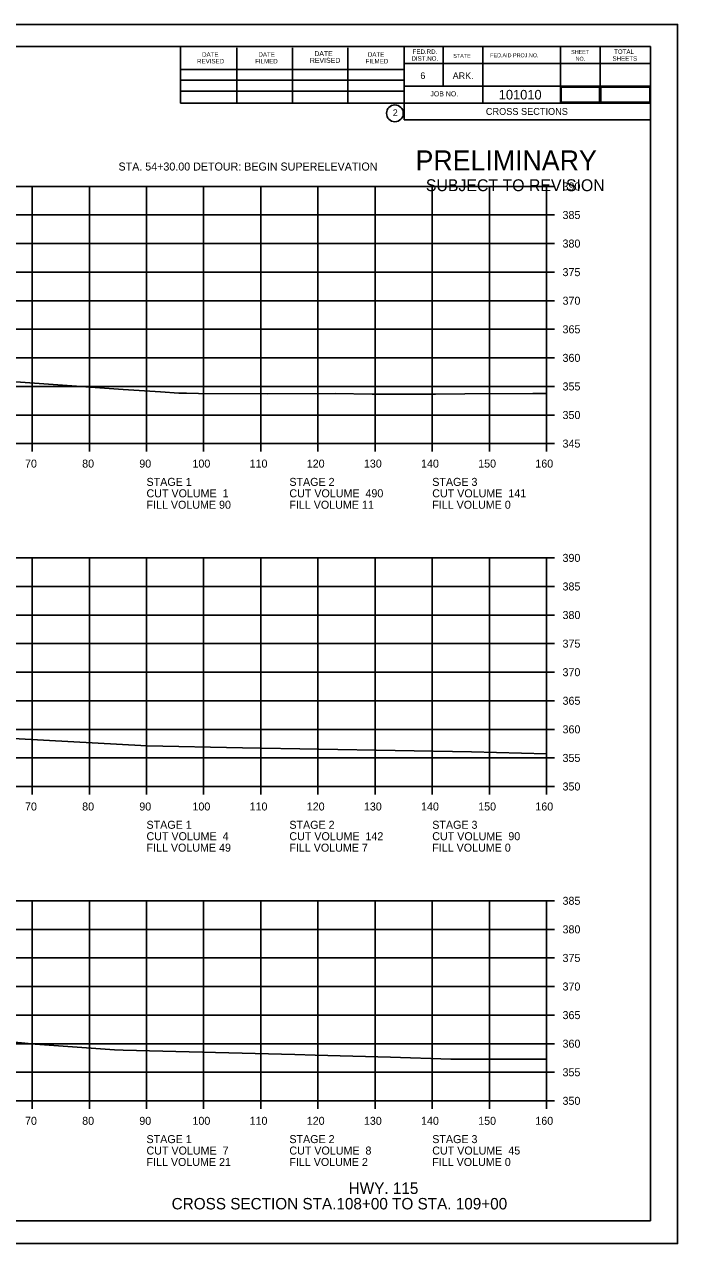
# Model space of a CAD drawing. Extents: x 1630712 to 1632516, y 782146 to 785403.
# Drawn here: x 1632401.6 to 1632515.9, y 783696.6 to 783910 of the extents above; entities that cross this region are included whole.
import ezdxf

# ---------------------------------------------------------------- set-up
doc = ezdxf.new("R2010")
doc.units = 0
for name, color, linetype in [('Page Number', 7, 'Continuous'), ('R_Annot', 7, 'Continuous'), ('R_Axis', 7, 'Continuous'), ('R_Axis Annot', 7, 'Continuous'), ('R_Border', 7, 'Continuous'), ('R_Border Notes', 7, 'Continuous'), ('R_Border Prem', 7, 'Continuous'), ('R_Draft', 7, 'Continuous'), ('R_Exist Surface', 7, 'Continuous'), ('R_Grid', 7, 'Continuous'), ('R_No Plot', 7, 'Continuous'), ('Total_Pages', 7, 'Continuous')]:
    doc.layers.add(name, color=color, linetype=linetype)

msp = doc.modelspace()

# ---------------------------------------------------------------- linework, layer by layer
at = {"layer": 'Page Number'}
msp.add_lwpolyline([(1632495.54, 783896.35), (1632502.21, 783896.35), (1632502.21, 783898.99), (1632495.54, 783898.99)], close=True, dxfattribs=at)
at = {"layer": 'R_Axis'}
for p, q in [((1632492.96, 783836.62), (1632492.96, 783881.62)), ((1632494.36, 783881.62), (1632492.96, 783881.62)), ((1632494.36, 783876.62), (1632492.96, 783876.62)), ((1632494.36, 783871.62), (1632492.96, 783871.62)), ((1632494.36, 783866.62), (1632492.96, 783866.62)), ((1632494.36, 783861.62), (1632492.96, 783861.62)), ((1632494.36, 783856.62), (1632492.96, 783856.62)), ((1632494.36, 783851.62), (1632492.96, 783851.62)), ((1632494.36, 783846.62), (1632492.96, 783846.62)), ((1632494.36, 783841.62), (1632492.96, 783841.62)), ((1632212.96, 783836.62), (1632492.96, 783836.62)), ((1632402.96, 783835.22), (1632402.96, 783836.62)), ((1632412.96, 783835.22), (1632412.96, 783836.62)), ((1632422.96, 783835.22), (1632422.96, 783836.62)), ((1632432.96, 783835.22), (1632432.96, 783836.62)), ((1632442.96, 783835.22), (1632442.96, 783836.62)), ((1632452.96, 783835.22), (1632452.96, 783836.62)), ((1632462.96, 783835.22), (1632462.96, 783836.62)), ((1632472.96, 783835.22), (1632472.96, 783836.62)), ((1632482.96, 783835.22), (1632482.96, 783836.62)), ((1632492.96, 783835.22), (1632492.96, 783836.62)), ((1632494.36, 783836.62), (1632492.96, 783836.62)), ((1632492.96, 783776.62), (1632492.96, 783816.62)), ((1632494.36, 783816.62), (1632492.96, 783816.62)), ((1632494.36, 783811.62), (1632492.96, 783811.62)), ((1632494.36, 783806.62), (1632492.96, 783806.62)), ((1632494.36, 783801.62), (1632492.96, 783801.62)), ((1632494.36, 783796.62), (1632492.96, 783796.62)), ((1632494.36, 783791.62), (1632492.96, 783791.62)), ((1632494.36, 783786.62), (1632492.96, 783786.62)), ((1632494.36, 783781.62), (1632492.96, 783781.62)), ((1632212.96, 783776.62), (1632492.96, 783776.62)), ((1632402.96, 783775.22), (1632402.96, 783776.62)), ((1632412.96, 783775.22), (1632412.96, 783776.62)), ((1632422.96, 783775.22), (1632422.96, 783776.62)), ((1632432.96, 783775.22), (1632432.96, 783776.62)), ((1632442.96, 783775.22), (1632442.96, 783776.62)), ((1632452.96, 783775.22), (1632452.96, 783776.62)), ((1632462.96, 783775.22), (1632462.96, 783776.62)), ((1632472.96, 783775.22), (1632472.96, 783776.62)), ((1632482.96, 783775.22), (1632482.96, 783776.62)), ((1632492.96, 783775.22), (1632492.96, 783776.62)), ((1632494.36, 783776.62), (1632492.96, 783776.62)), ((1632492.96, 783721.62), (1632492.96, 783756.62)), ((1632494.36, 783756.62), (1632492.96, 783756.62)), ((1632494.36, 783751.62), (1632492.96, 783751.62)), ((1632494.36, 783746.62), (1632492.96, 783746.62)), ((1632494.36, 783741.62), (1632492.96, 783741.62)), ((1632494.36, 783736.62), (1632492.96, 783736.62)), ((1632494.36, 783731.62), (1632492.96, 783731.62)), ((1632494.36, 783726.62), (1632492.96, 783726.62)), ((1632212.96, 783721.62), (1632492.96, 783721.62)), ((1632402.96, 783720.22), (1632402.96, 783721.62)), ((1632412.96, 783720.22), (1632412.96, 783721.62)), ((1632422.96, 783720.22), (1632422.96, 783721.62)), ((1632432.96, 783720.22), (1632432.96, 783721.62)), ((1632442.96, 783720.22), (1632442.96, 783721.62)), ((1632452.96, 783720.22), (1632452.96, 783721.62)), ((1632462.96, 783720.22), (1632462.96, 783721.62)), ((1632472.96, 783720.22), (1632472.96, 783721.62)), ((1632482.96, 783720.22), (1632482.96, 783721.62)), ((1632492.96, 783720.22), (1632492.96, 783721.62)), ((1632494.36, 783721.62), (1632492.96, 783721.62))]:
    msp.add_line(p, q, dxfattribs=at)
at = {"layer": 'R_Border'}
for p, q in [((1632194.96, 783906.08), (1632511.14, 783906.08)), ((1632428.88, 783896.2), (1632428.88, 783906.08)), ((1632438.74, 783896.2), (1632438.74, 783905.88)), ((1632448.5, 783896.2), (1632448.5, 783905.88)), ((1632458.18, 783896.2), (1632458.18, 783905.88)), ((1632468.04, 783906.08), (1632468.04, 783893.28)), ((1632474.88, 783906.08), (1632474.88, 783899.14)), ((1632481.82, 783906.08), (1632481.82, 783896.2)), ((1632495.4, 783906.08), (1632495.4, 783896.2)), ((1632502.34, 783906.08), (1632502.34, 783896.2)), ((1632511.14, 783700.62), (1632511.14, 783906.08)), ((1632511.14, 783903.14), (1632468.04, 783903.14)), ((1632511.14, 783903.16), (1632511.14, 783903.16)), ((1632428.88, 783902.06), (1632468.04, 783902.06)), ((1632428.88, 783900.2), (1632468.04, 783900.2)), ((1632511.14, 783899.14), (1632468.04, 783899.14)), ((1632471, 783899.14), (1632511.14, 783899.14)), ((1632428.88, 783896.2), (1632428.88, 783898.26)), ((1632428.88, 783898.26), (1632468.04, 783898.26)), ((1632511.14, 783896.2), (1632428.88, 783896.2)), ((1632468.04, 783893.28), (1632511.14, 783893.28)), ((1632511.14, 783700.62), (1632194.96, 783700.62))]:
    msp.add_line(p, q, dxfattribs=at)
msp.add_circle((1632466.43, 783894.41), 1.47, dxfattribs=at)
at = {"layer": 'R_Exist Surface'}
for points in [[(1632382.87, 783848.65), (1632418.85, 783846.11), (1632425.38, 783845.65), (1632428.63, 783845.43), (1632429.98, 783845.42), (1632432.07, 783845.41), (1632444.2, 783845.35), (1632455.99, 783845.38), (1632462.44, 783845.26), (1632473.51, 783845.29), (1632478.64, 783845.34), (1632490.58, 783845.4), (1632492.96, 783845.41)], [(1632387.86, 783785.68), (1632423, 783783.71), (1632439.75, 783783.4), (1632479.84, 783782.71), (1632492.96, 783782.36)], [(1632385.36, 783733.3), (1632403.49, 783731.55), (1632417.36, 783730.55), (1632418.88, 783730.51), (1632448.92, 783729.7), (1632452.5, 783729.6), (1632465.65, 783729.24), (1632476.2, 783728.93), (1632491.31, 783728.93), (1632492.96, 783728.9)]]:
    msp.add_lwpolyline(points, dxfattribs=at)
at = {"layer": 'R_Grid'}
for p, q in [((1632212.96, 783881.62), (1632492.96, 783881.62)), ((1632402.96, 783836.62), (1632402.96, 783881.62)), ((1632412.96, 783836.62), (1632412.96, 783881.62)), ((1632422.96, 783836.62), (1632422.96, 783881.62)), ((1632432.96, 783836.62), (1632432.96, 783881.62)), ((1632442.96, 783836.62), (1632442.96, 783881.62)), ((1632452.96, 783836.62), (1632452.96, 783881.62)), ((1632462.96, 783836.62), (1632462.96, 783881.62)), ((1632472.96, 783836.62), (1632472.96, 783881.62)), ((1632482.96, 783836.62), (1632482.96, 783881.62)), ((1632492.96, 783836.62), (1632492.96, 783881.62)), ((1632212.96, 783876.62), (1632492.96, 783876.62)), ((1632212.96, 783871.62), (1632492.96, 783871.62)), ((1632212.96, 783866.62), (1632492.96, 783866.62)), ((1632212.96, 783861.62), (1632492.96, 783861.62)), ((1632212.96, 783856.62), (1632492.96, 783856.62)), ((1632212.96, 783851.62), (1632492.96, 783851.62)), ((1632212.96, 783846.62), (1632492.96, 783846.62)), ((1632212.96, 783841.62), (1632492.96, 783841.62)), ((1632212.96, 783836.62), (1632492.96, 783836.62)), ((1632212.96, 783816.62), (1632492.96, 783816.62)), ((1632402.96, 783776.62), (1632402.96, 783816.62)), ((1632412.96, 783776.62), (1632412.96, 783816.62)), ((1632422.96, 783776.62), (1632422.96, 783816.62)), ((1632432.96, 783776.62), (1632432.96, 783816.62)), ((1632442.96, 783776.62), (1632442.96, 783816.62)), ((1632452.96, 783776.62), (1632452.96, 783816.62)), ((1632462.96, 783776.62), (1632462.96, 783816.62)), ((1632472.96, 783776.62), (1632472.96, 783816.62)), ((1632482.96, 783776.62), (1632482.96, 783816.62)), ((1632492.96, 783776.62), (1632492.96, 783816.62)), ((1632212.96, 783811.62), (1632492.96, 783811.62)), ((1632212.96, 783806.62), (1632492.96, 783806.62)), ((1632212.96, 783801.62), (1632492.96, 783801.62)), ((1632212.96, 783796.62), (1632492.96, 783796.62)), ((1632212.96, 783791.62), (1632492.96, 783791.62)), ((1632212.96, 783786.62), (1632492.96, 783786.62)), ((1632212.96, 783781.62), (1632492.96, 783781.62)), ((1632212.96, 783776.62), (1632492.96, 783776.62)), ((1632212.96, 783756.62), (1632492.96, 783756.62)), ((1632402.96, 783721.62), (1632402.96, 783756.62)), ((1632412.96, 783721.62), (1632412.96, 783756.62)), ((1632422.96, 783721.62), (1632422.96, 783756.62)), ((1632432.96, 783721.62), (1632432.96, 783756.62)), ((1632442.96, 783721.62), (1632442.96, 783756.62)), ((1632452.96, 783721.62), (1632452.96, 783756.62)), ((1632462.96, 783721.62), (1632462.96, 783756.62)), ((1632472.96, 783721.62), (1632472.96, 783756.62)), ((1632482.96, 783721.62), (1632482.96, 783756.62)), ((1632492.96, 783721.62), (1632492.96, 783756.62)), ((1632212.96, 783751.62), (1632492.96, 783751.62)), ((1632212.96, 783746.62), (1632492.96, 783746.62)), ((1632212.96, 783741.62), (1632492.96, 783741.62)), ((1632212.96, 783736.62), (1632492.96, 783736.62)), ((1632212.96, 783731.62), (1632492.96, 783731.62)), ((1632212.96, 783726.62), (1632492.96, 783726.62)), ((1632212.96, 783721.62), (1632492.96, 783721.62))]:
    msp.add_line(p, q, dxfattribs=at)
at = {"layer": 'R_No Plot'}
for p, q in [((1632182.56, 783909.97), (1632515.9, 783909.97)), ((1632182.56, 783696.64), (1632515.9, 783696.64))]:
    msp.add_line(p, q, dxfattribs=at)
msp.add_lwpolyline([(1632182.56, 783909.97), (1632515.9, 783909.97), (1632515.9, 783696.63), (1632182.56, 783696.63)], close=True, dxfattribs=at)
at = {"layer": 'Total_Pages'}
msp.add_lwpolyline([(1632502.44, 783896.35), (1632511.05, 783896.35), (1632511.05, 783898.99), (1632502.44, 783898.99)], close=True, dxfattribs=at)

# ---------------------------------------------------------------- texts
at = {"layer": 'R_Annot'}
msp.add_text('STA. 54+30.00 DETOUR: BEGIN SUPERELEVATION', height=1.4, dxfattribs=at).set_placement((1632418.06, 783884.4))
at = {"layer": 'R_Axis Annot'}
for s, p in [('390', (1632495.76, 783880.92)), ('385', (1632495.76, 783875.92)), ('380', (1632495.76, 783870.92)), ('375', (1632495.76, 783865.92)), ('370', (1632495.76, 783860.92)), ('365', (1632495.76, 783855.92)), ('360', (1632495.76, 783850.92)), ('355', (1632495.76, 783845.92)), ('350', (1632495.76, 783840.92)), ('345', (1632495.76, 783835.92)), ('70', (1632401.7, 783832.42)), ('80', (1632411.7, 783832.42)), ('90', (1632421.7, 783832.42)), ('100', (1632431, 783832.42)), ('110', (1632441, 783832.42)), ('120', (1632451, 783832.42)), ('130', (1632461, 783832.42)), ('140', (1632471, 783832.42)), ('150', (1632481, 783832.42)), ('160', (1632491, 783832.42)), ('STAGE 1', (1632422.96, 783829.22)), ('STAGE 2', (1632447.96, 783829.22)), ('STAGE 3', (1632472.96, 783829.22)), ('CUT VOLUME  1', (1632422.96, 783827.22)), ('CUT VOLUME  490', (1632447.96, 783827.22)), ('CUT VOLUME  141', (1632472.96, 783827.22)), ('FILL VOLUME 90', (1632422.96, 783825.22)), ('FILL VOLUME 11', (1632447.96, 783825.22)), ('FILL VOLUME 0', (1632472.96, 783825.22)), ('390', (1632495.76, 783815.92)), ('385', (1632495.76, 783810.92)), ('380', (1632495.76, 783805.92)), ('375', (1632495.76, 783800.92)), ('370', (1632495.76, 783795.92)), ('365', (1632495.76, 783790.92)), ('360', (1632495.76, 783785.92)), ('355', (1632495.76, 783780.92)), ('350', (1632495.76, 783775.92)), ('70', (1632401.7, 783772.42)), ('80', (1632411.7, 783772.42)), ('90', (1632421.7, 783772.42)), ('100', (1632431, 783772.42)), ('110', (1632441, 783772.42)), ('120', (1632451, 783772.42)), ('130', (1632461, 783772.42)), ('140', (1632471, 783772.42)), ('150', (1632481, 783772.42)), ('160', (1632491, 783772.42)), ('STAGE 1', (1632422.96, 783769.22)), ('STAGE 2', (1632447.96, 783769.22)), ('STAGE 3', (1632472.96, 783769.22)), ('CUT VOLUME  4', (1632422.96, 783767.22)), ('CUT VOLUME  142', (1632447.96, 783767.22)), ('CUT VOLUME  90', (1632472.96, 783767.22)), ('FILL VOLUME 49', (1632422.96, 783765.22)), ('FILL VOLUME 7', (1632447.96, 783765.22)), ('FILL VOLUME 0', (1632472.96, 783765.22)), ('385', (1632495.76, 783755.92)), ('380', (1632495.76, 783750.92)), ('375', (1632495.76, 783745.92)), ('370', (1632495.76, 783740.92)), ('365', (1632495.76, 783735.92)), ('360', (1632495.76, 783730.92)), ('355', (1632495.76, 783725.92)), ('350', (1632495.76, 783720.92)), ('70', (1632401.7, 783717.42)), ('80', (1632411.7, 783717.42)), ('90', (1632421.7, 783717.42)), ('100', (1632431, 783717.42)), ('110', (1632441, 783717.42)), ('120', (1632451, 783717.42)), ('130', (1632461, 783717.42)), ('140', (1632471, 783717.42)), ('150', (1632481, 783717.42)), ('160', (1632491, 783717.42)), ('STAGE 1', (1632422.96, 783714.22)), ('STAGE 2', (1632447.96, 783714.22)), ('STAGE 3', (1632472.96, 783714.22)), ('CUT VOLUME  7', (1632422.96, 783712.22)), ('CUT VOLUME  8', (1632447.96, 783712.22)), ('CUT VOLUME  45', (1632472.96, 783712.22)), ('FILL VOLUME 21', (1632422.96, 783710.22)), ('FILL VOLUME 2', (1632447.96, 783710.22)), ('FILL VOLUME 0', (1632472.96, 783710.22))]:
    msp.add_text(s, height=1.4, dxfattribs=at).set_placement(p)
at = {"layer": 'R_Border'}
for s, height, p in [('DATE', 0.782, (1632432.68, 783904.32)), ('DATE', 0.782, (1632442.54, 783904.32)), ('DATE', 0.879, (1632452.32, 783904.42)), ('DATE', 0.782, (1632461.7, 783904.32)), ('FED.RD.', 0.782, (1632469.52, 783904.8)), ('STATE', 0.684, (1632476.64, 783904.12)), ('FED.AID PROJ.NO.', 0.684, (1632483.1, 783904.22)), ('SHEET', 0.684, (1632497.26, 783904.8)), ('TOTAL', 0.782, (1632504.78, 783904.8)), ('REVISED', 0.782, (1632431.8, 783903.14)), ('FILMED', 0.782, (1632441.96, 783903.14)), ('REVISED', 0.879, (1632451.54, 783903.24)), ('FILMED', 0.782, (1632461.3, 783903.14)), ('DIST.NO.', 0.782, (1632469.32, 783903.62)), ('NO.', 0.684, (1632498.04, 783903.62)), ('SHEETS', 0.782, (1632504.5, 783903.62)), ('6', 1.17, (1632470.88, 783900.4)), ('ARK.', 1.172, (1632476.54, 783900.4)), ('JOB NO.', 0.879, (1632472.64, 783897.38)), ('2', 1.17, (1632466.05, 783893.93))]:
    msp.add_text(s, height=height, rotation=360, dxfattribs=at).set_placement(p)
at = {"layer": 'R_Border Notes'}
for s, height, p in [('101010', 1.68, (1632484.6, 783896.83)), ('CROSS SECTIONS', 1.2, (1632482.34, 783894.14))]:
    msp.add_text(s, height=height, dxfattribs=at).set_placement(p)
at = {"layer": 'R_Border Prem'}
for s, height, p in [('PRELIMINARY', 3.5, (1632470.03, 783884.42)), ('SUBJECT TO REVISION', 2.0751, (1632471.84, 783880.79))]:
    msp.add_text(s, height=height, rotation=360, dxfattribs=at).set_placement(p)
at = {"layer": 'R_Draft'}
for s, p in [('HWY. 115', (1632458.34, 783705.33)), ('CROSS SECTION STA.108+00 TO STA. 109+00', (1632427.36, 783702.62))]:
    msp.add_text(s, height=2, dxfattribs=at).set_placement(p)

doc.saveas('drawing.dxf')
